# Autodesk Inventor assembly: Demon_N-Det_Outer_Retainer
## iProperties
Shininess: 64.0
Length Units: 11269
Angle Units: 11279
Time Units: 11290
Mass Units: 11283
Length Display Precision: 3
Angle Display Precision: 2
Compacted: True
Created: 2005-04
Part Number: Demon_N-Det_Outer_Retainer
Document SubType Name: Assembly
Designer: John Blackburn
Manufacturer: Standard
Standards Organization: Custom
Density: 0.0
Volumn: 0.0
Area: 0.0
PropertySet Name: Model Information
Control State: 0
Master: False
Checked Out: False
Author: John Blackburn
